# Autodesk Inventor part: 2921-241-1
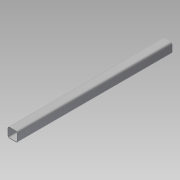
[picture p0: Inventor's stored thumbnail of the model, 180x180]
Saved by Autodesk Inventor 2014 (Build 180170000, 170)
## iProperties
Company: NHTSA/VRTC
Created: 2011-11
Part Number: 2921-241-1
Material: Steel
Document SubType Name: Modeling
Designer: Dave Walker
Density: 7.85 g/cm^3
Project: CHILD SIDE IMPACT SLED
Description: T.S. 2" x 2" x 1/8" x 782.3mm (30.80")
Mass: 3444.48 g
Surface Area: 2775.23 cm^2
Volume: 438.787 cm^3
Stock Number: IMPACTOR FRAME TUBE 1
Appearance: Steel
Author: Dave Walker
Title: Impactor Frame Tube 1
Subject: Child Side Impact Sled
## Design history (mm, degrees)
node "Sketch1"
node "2921-105-11"
workplane "Work Plane4"
workplane "Work Plane5"
node "2921-105-1"
node "Base1"
